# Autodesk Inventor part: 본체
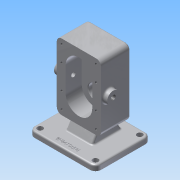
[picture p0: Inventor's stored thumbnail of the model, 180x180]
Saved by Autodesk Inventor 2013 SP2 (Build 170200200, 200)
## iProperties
Created: 2026-10
Part Number: 본체
Material: 알루미늄 6061
Document SubType Name: Modeling
Designer: a
Density: 2.71 g/cm^3
Mass: 1476.95 g
Surface Area: 818.113 cm^2
Volume: 545.001 cm^3
Author: a
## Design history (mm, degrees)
sketch "스케치1"
  geometry: L1 (-31, -60)-(31, -60); L2 (40, -51)-(40, 51); L3 (31, 60)-(-31, 60); L4 (-40, 51)-(-40, -51); L5 (-40, -60)-(40, 60); L6 (40, -60)-(-40, 60); A1 r 9 centre (-31, 51) between (-31, 60) and (-40, 51); A2 r 9 centre (31, 51) between (40, 51) and (31, 60); A3 r 9 centre (31, -51) between (31, -60) and (40, -51); A4 r 9 centre (-31, -51) between (-40, -51) and (-31, -60); 1 further point
  constraints: 12 end point, 8 point on circle, 8 point on line, 8 tangent, 4 centre point, 2 midpoint, 2 parallel, 1 horizontal, 1 perpendicular
  dimensions: "d0" = 80 distance of L5.end L6.end; "d2" = 120 distance of L6.start L5.end; "d3" = 9 radius of A1; "d4" = 9 radius of A2; "d5" = 9 radius of A3; "d6" = 9 radius of A4
extrude "돌출1" new body sketch "스케치1" distance "d7" = 53; taper "d8" = 0 deg
sketch "스케치2"
  geometry: L1 (0, -46)-(0, -46); L2 (24, -22)-(24, 22); L3 (0, 46)-(0, 46); L4 (-24, 22)-(-24, -22); L5 (-24, -46)-(24, 46); L6 (24, -46)-(-24, 46); A1 r 24 centre (0, 22) between (0, 46) and (-24, 22); A2 r 24 centre (0, 22) between (24, 22) and (0, 46); A3 r 24 centre (0, -22) between (0, -46) and (24, -22); A4 r 24 centre (0, -22) between (-24, -22) and (0, -46); 1 further point
  constraints: 12 end point, 8 point on circle, 8 point on line, 8 tangent, 4 centre point, 2 midpoint, 2 parallel, 1 horizontal, 1 perpendicular
  dimensions: "d9" = 48 distance of L5.end L6.end; "d11" = 24 radius of A1; "d12" = 24 radius of A2; "d13" = 24 radius of A3; "d14" = 24 radius of A4; "d15" = 44 distance of A3.centre A2.centre
extrude "돌출2" cut sketch "스케치2" distance "d16" = 29; taper "d17" = 0 deg
sketch "스케치3"
  geometry: C1 r 19.02 at (0, 22); 1 further point
  constraints: 1 centre point, 1 vertical alignment
  dimensions: "d18" = 22 distance of point (0, 0) C1.centre
extrude "돌출3" join sketch "스케치3" distance "d19" = 17; taper "d20" = 0 deg
sketch "스케치4"
  geometry: L1 (60, 0)-(60, -53) reference; L2 (60, -53)-(41.02, -53) reference; L3 (41.02, -53)-(41.02, -70) reference; L4 (41.02, -70)-(2.98, -70) reference; L5 (2.98, -70)-(2.98, -53) reference; L6 (2.98, -53)-(-60, -53) reference; L7 (-60, -53)-(-60, 0) reference; L8 (-60, 0)-(-46, 0) reference; L9 (-46, 0)-(-46, -29) reference; L10 (-46, -29)-(46, -29) reference; L11 (46, -29)-(46, 0) reference; L12 (46, 0)-(60, 0) reference; L13 (22, -70)-(22, -29); L14 (22, -29)-(34.5, -29); L15 (34.5, -29)-(34.5, -44); L16 (34.5, -44)-(30.5, -44); L17 (30.5, -44)-(30.5, -62.7); L18 (30.5, -62.7)-(36, -62.7); L19 (36, -62.7)-(36, -70); L20 (22, -70)-(36, -70); 1 further point
  constraints: 16 end point, 4 perpendicular, 3 parallel, 3 point on line, 1 midpoint
  dimensions: "d21" = 15 distance of L14.end L15.end; "d23" = 7.3 distance of L18.end L19.end; "d24" = 25 diameter of L15 L13; "d25" = 17 diameter of L17 L13; "d26" = 28 diameter of L19 L13
revolve "회전1" sketch "스케치4" stored, may be unused: angle "d27" = 90 deg
sketch "스케치5"
  geometry: C1 r 12.5 at (0, -22); A1 r 24 centre (0, -22) between (-24, -22) and (24, -22) reference; 1 further point
  constraints: 1 centre point, 1 coincident
  dimensions: "d28" = 25 diameter of C1
extrude "돌출4" cut sketch "스케치5" distance "d30" = 15; taper "d31" = 0 deg
sketch "스케치6"
  geometry: L1 (0, 102)-(0, 0) reference; C1 r 11 at (14, 51); 2 further points
  constraints: 1 centre point, 1 horizontal alignment, 1 midpoint
  dimensions: "d32" = 22 diameter of C1; "d34" = 14 distance of point (0, 51) C1.centre
extrude "돌출5" join sketch "스케치6" distance "d35" = 8; taper "d36" = 0 deg
sketch "스케치7"
  geometry: L1 (0, 0)-(0, 102) reference; C1 r 11 at (-14, 51); 2 further points
  constraints: 1 centre point, 1 horizontal alignment, 1 midpoint
  dimensions: "d37" = 22 diameter of C1; "d39" = 14 distance of point (0, 51) C1.centre
extrude "돌출6" join sketch "스케치7" distance "d40" = 8; taper "d41" = 0 deg
sketch "스케치8"
  geometry: C1 r 11 at (0, 0) reference; 2 further points
  constraints: 1 coincident
hole "구멍1" sketch "스케치8" at (0, 0) diameter "d42" = 8; stored, may be unused: countersink angle "d48" = 90 deg, drill point angle "d50" = 118 deg; dims "d43" = 9, "d44" = 0.62479, "d45" = 7.985, "d46" = 4, "d47" = 2, "d49" = 8
sketch "스케치9"
  geometry: C1 r 11 at (0, 0) reference; 2 further points
  constraints: 1 coincident
hole "구멍2" sketch "스케치9" at (0, 0) diameter "d51" = 8; stored, may be unused: countersink angle "d57" = 90 deg, drill point angle "d59" = 118 deg; dims "d52" = 9, "d53" = 0.62479, "d54" = 7.985, "d55" = 4, "d56" = 2, "d58" = 8
sketch "스케치10"
  geometry: A1 r 24 centre (0, 22) between (24, 22) and (-24, 22) reference; A2 r 24 centre (0, -22) between (-24, -22) and (24, -22) reference; A3 r 9 centre (-31, 51) between (-31, 60) and (-40, 51) reference; A4 r 9 centre (-31, -51) between (-40, -51) and (-31, -60) reference; A5 r 9 centre (31, -51) between (31, -60) and (40, -51) reference; A6 r 9 centre (31, 51) between (40, 51) and (31, 60) reference; 9 further points
  constraints: 4 coincident, 4 horizontal alignment
hole "구멍3" sketch "스케치10" at (-31, 51), (31, 51), (-31, -51), (31, -51), (-31, 22), (31, 22), (-31, -22), (31, -22) diameter "d60" = 4.134; stored, may be unused: countersink angle "d64" = 90 deg, drill point angle "d66" = 118 deg; dims "d61" = 10, "d62" = 4, "d63" = 2, "d65" = 12
chamfer "모따기1" distance "d67" = 1; stored, may be unused: second distance "d68" = 2, angle "d69" = 45 deg
chamfer "모따기2" distance "d70" = 1; stored, may be unused: second distance "d71" = 2, angle "d72" = 45 deg
node "작업 평면1"
sketch "스케치12"
  geometry: L1 (-19, -30)-(81, -30); L2 (91, -20)-(91, 60); L3 (81, 70)-(-19, 70); L4 (-29, 60)-(-29, -20); L5 (0, 0)-(62, 0) reference; L6 (50.02, 70)-(11.98, 70) reference; A1 r 10 centre (-19, -20) between (-29, -20) and (-19, -30); A2 r 10 centre (-19, 60) between (-19, 70) and (-29, 60); A3 r 10 centre (81, 60) between (91, 60) and (81, 70); A4 r 10 centre (81, -20) between (81, -30) and (91, -20); 4 further points
  constraints: 8 end point, 8 point on circle, 8 tangent, 6 point on line, 4 centre point, 2 parallel, 1 collinear, 1 horizontal, 1 perpendicular
  dimensions: "d75" = 100 distance of point (-29, 70) point (-29, -30); "d77" = 120 distance of point (-29, -30) point (91, -30); "d78" = 60 distance from line of point (31, 0) L4; "d79" = 10 radius of A1; "d80" = 10 radius of A2; "d81" = 10 radius of A3; "d82" = 10 radius of A4
extrude "돌출7" join sketch "스케치12" distance "d83" = 10; taper "d84" = 0 deg
sketch "스케치14"
  geometry: L1 (-60, -53)-(-60, 0) reference; L2 (-60, 0)-(-46, 0) reference; L3 (-46, 0)-(-46, -29) reference; L4 (-46, -29)-(-35.5, -29) reference; L5 (-35.5, -29)-(-34.5, -30) reference; L6 (-34.5, -30)-(-34.5, -44) reference; L7 (-34.5, -44)-(-9.5, -44) reference; L8 (-9.5, -44)-(-9.5, -30) reference; L9 (-9.5, -30)-(-8.5, -29) reference; L10 (-8.5, -29)-(8.5, -29) reference; L11 (8.5, -29)-(9.5, -30) reference; L12 (9.5, -30)-(9.5, -44) reference; L13 (9.5, -44)-(13.5, -44) reference; L14 (13.5, -44)-(13.5, -62.7) reference; L15 (13.5, -62.7)-(8, -62.7) reference; L16 (8, -62.7)-(8, -70) reference; L17 (8, -70)-(2.98, -70) reference; L18 (2.98, -70)-(2.98, -53) reference; L19 (2.98, -53)-(-60, -53) reference; L20 (60, 0)-(60, -53) reference; L21 (60, -53)-(41.02, -53) reference; L22 (41.02, -53)-(41.02, -70) reference; L23 (41.02, -70)-(36, -70) reference; L24 (36, -70)-(36, -62.7) reference; L25 (36, -62.7)-(30.5, -62.7) reference; L26 (30.5, -62.7)-(30.5, -44) reference; L27 (30.5, -44)-(34.5, -44) reference; L28 (34.5, -44)-(34.5, -30) reference; L29 (34.5, -30)-(35.5, -29) reference; L30 (35.5, -29)-(46, -29) reference; L31 (46, -29)-(46, 0) reference; L32 (46, 0)-(60, 0) reference; L33 (-90, 30)-(-80, 30) reference; L34 (-80, 30)-(-80, -70) reference; L35 (-80, -70)-(-90, -70) reference; L36 (-90, -70)-(-90, 30) reference; L37 (-60, -11.547)-(-80, 0); L38 (-60, -41.453)-(-80, -53); L39 (-60, -11.547)-(-60, -41.453); L40 (-80, 0)-(-80, -53); 1 further point
  constraints: 8 end point, 4 point on line, 2 collinear
  dimensions: "d85" = 53 distance of L38.end L37.end; "d86" = 60 deg angle of L34 L38; "d87" = 60 deg angle of L34 L37; "d88" = 17 distance of L34.end L38.end
extrude "돌출8" join sketch "스케치14" stored distance "d89" = 48; taper "d90" = 0 deg
fillet "모깎기2" dims "d91" = 0.5
sketch "스케치15"
  geometry: A1 r 10 centre (81, -20) between (81, -30) and (91, -20) reference; A2 r 10 centre (81, 60) between (91, 60) and (81, 70) reference; A3 r 10 centre (-19, 60) between (-19, 70) and (-29, 60) reference; A4 r 10 centre (-19, -20) between (-29, -20) and (-19, -30) reference; 5 further points
  constraints: 4 coincident
hole "구멍4" sketch "스케치15" at (-19, 60), (81, 60), (-19, -20), (81, -20) diameter "d95" = 10; stored, may be unused: countersink angle "d99" = 90 deg, drill point angle "d101" = 118 deg; dims "d96" = 10, "d97" = 4, "d98" = 2, "d100" = 12
fillet "모깎기3" dims "d102" = 3
fillet "모깎기4" dims "d103" = 3
fillet "모깎기5" dims "d104" = 3
fillet "모깎기6" dims "d105" = 3
fillet "모깎기7" dims "d106" = 3
sketch "스케치16" dims "d0" = 80, "d2" = 120, "d3" = 9, "d4" = 9, "d5" = 9, "d6" = 9
  geometry: L1 (-19, -30)-(81, -30) reference; 2 further points
  constraints: 1 vertical alignment, 1 other
  dimensions: "d108" = 10 distance from line of L1 point (31, -20)
feature "엠보싱1" sketch "스케치16" dims "d0" = 80, "d2" = 120, "d3" = 9, "d4" = 9, "d5" = 9, "d6" = 9, "d9" = 48, "d11" = 24, "d12" = 24, "d13" = 24, "d14" = 24, "d15" = 44, "d109" = 0.5, "d110" = 0
chamfer "모따기4" distance "d111" = 0.7; stored, may be unused: second distance "d112" = 2, angle "d113" = 30 deg
fillet "모깎기8" dims "d114" = 3
node "솔리드1"
node "절단 모서리 투영1"
node "절단 모서리 투영2"
